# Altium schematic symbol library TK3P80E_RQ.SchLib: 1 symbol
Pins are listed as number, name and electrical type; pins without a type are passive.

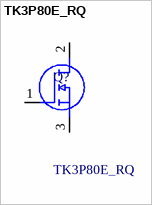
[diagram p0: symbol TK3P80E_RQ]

## TK3P80E_RQ
designator Q?
MOSFET PWR MOS PD=80W  F=1MHZ; Manufacturer_Name: Toshiba; Manufacturer_Part_Number: TK3P80E,RQ; Geometry.Height: 2.4mm
footprint TK3P80ERQ
pins: 1 G, 2 D, 3 S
